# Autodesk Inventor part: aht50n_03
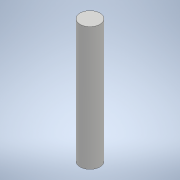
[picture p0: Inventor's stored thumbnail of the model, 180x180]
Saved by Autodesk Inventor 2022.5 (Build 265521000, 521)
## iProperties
Created: 2019-12
Part Number: aht50n_03
Material: 一般
Document SubType Name: Modeling
Designer: ImaoCorp
Density: 1 g/cm^3
Appearance: 既定
Author: ImaoCorp
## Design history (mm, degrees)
feature "aht50n_03"
node "ソリッド1"
